Omron CX-Programmer project NewProject (CX-Programmer 6.11)

# PLC Elevator: CPM1(CPM1A) CPU20

## Global symbols (name address type ; comment)
200.01 BOOL  ; Elevator @ Level 2
200.02 BOOL  ; Elevator @ Level 3
0.00 BOOL  ; GN Start - 4th
0.01 BOOL  ; BK Start - 3rd
0.02 BOOL  ; BK Jog - 2nd
0.03 BOOL  ; RD EStop - 1st
0.04 BOOL  ; RD Stop - UP
0.05 BOOL  ; RD Stop - DN
0.07 BOOL  ; Basement
0.08 BOOL  ; Level 1
0.09 BOOL  ; Level 4
0.10 BOOL  ; Level 3
0.11 BOOL  ; Level 2
10.01 BOOL  ; Up Motor
10.02 BOOL  ; Down Motor
200.00 BOOL  ; Elevator @ Level 1
200.03 BOOL  ; Elevator @ Level 4
200.04 BOOL  ; Call Button 4th
200.05 BOOL  ; Call Button 3rd
200.06 BOOL  ; Call Button 2nd
200.07 BOOL  ; Call Button 1st
200.08 BOOL  ; Manual Up
200.09 BOOL  ; Manual Down
200.10 BOOL  ; Elevator @ Basement
210.01 BOOL  ; Manual Up
210.02 BOOL  ; Manual Down

## Program Elevator (no task)

### Section Section1

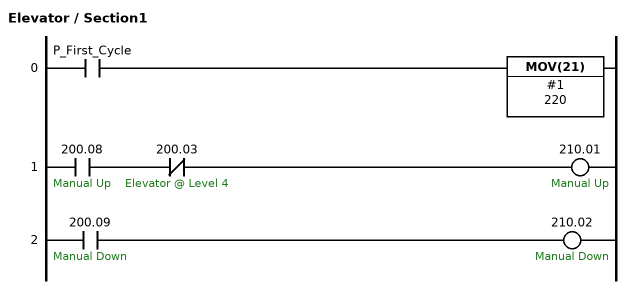
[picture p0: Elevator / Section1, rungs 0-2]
; rung 0
LD P_First_Cycle
MOV(21) #1 220
; rung 1
LD 200.08  ; Manual Up
ANDNOT 200.03  ; Elevator @ Level 4
OUT 210.01  ; Manual Up
; rung 2
LD 200.09  ; Manual Down
OUT 210.02  ; Manual Down

### Section Inputs

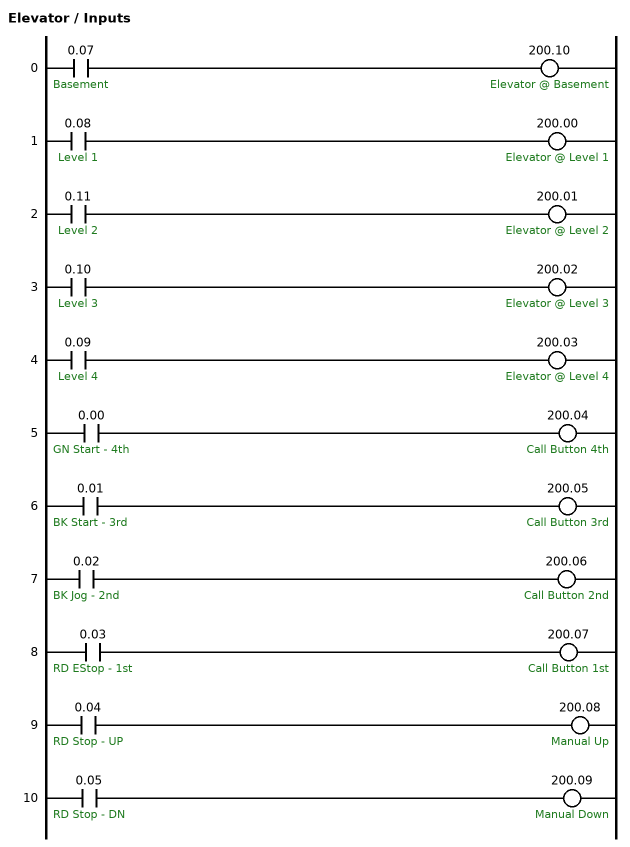
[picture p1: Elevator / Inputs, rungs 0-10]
; rung 0
LD 0.07  ; Basement
OUT 200.10  ; Elevator @ Basement
; rung 1
LD 0.08  ; Level 1
OUT 200.00  ; Elevator @ Level 1
; rung 2
LD 0.11  ; Level 2
OUT 200.01  ; Elevator @ Level 2
; rung 3
LD 0.10  ; Level 3
OUT 200.02  ; Elevator @ Level 3
; rung 4
LD 0.09  ; Level 4
OUT 200.03  ; Elevator @ Level 4
; rung 5
LD 0.00  ; GN Start - 4th
OUT 200.04  ; Call Button 4th
; rung 6
LD 0.01  ; BK Start - 3rd
OUT 200.05  ; Call Button 3rd
; rung 7
LD 0.02  ; BK Jog - 2nd
OUT 200.06  ; Call Button 2nd
; rung 8
LD 0.03  ; RD EStop - 1st
OUT 200.07  ; Call Button 1st
; rung 9
LD 0.04  ; RD Stop - UP
OUT 200.08  ; Manual Up
; rung 10
LD 0.05  ; RD Stop - DN
OUT 200.09  ; Manual Down

### Section Outputs

### Section Section3
; rung 0
END(01)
